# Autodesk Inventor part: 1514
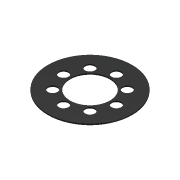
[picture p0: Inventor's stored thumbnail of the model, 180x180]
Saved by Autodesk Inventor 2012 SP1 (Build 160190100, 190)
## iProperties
Created: 2012-02
Part Number: 1514
Material: Silicone
Document SubType Name: Modeling
Designer: LACO
Density: 1.25 g/cm^3
Mass: 44.7245 g
Surface Area: 313.145 cm^2
Volume: 35.7796 cm^3
Author: LACO
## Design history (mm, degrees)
sketch "Sketch4"
  geometry: C1 r 9.525 at (-36.37, 36.37); C2 r 9.525 at (0, 51.435); C3 r 9.525 at (36.37, 36.37); C4 r 9.525 at (51.435, 0); C5 r 9.525 at (36.37, -36.37); C6 r 9.525 at (0, -51.435); C7 r 9.525 at (-36.37, -36.37); C8 r 9.525 at (-51.435, 0); C9 r 81.915 at (0, 0); C10 r 38.735 at (0, 0)
  constraints: 10 centre point
extrude "Extrusion1" new body sketch "Sketch4" distance "d38" = 2.54; taper "d39" = 0 deg
body "Solid2"
